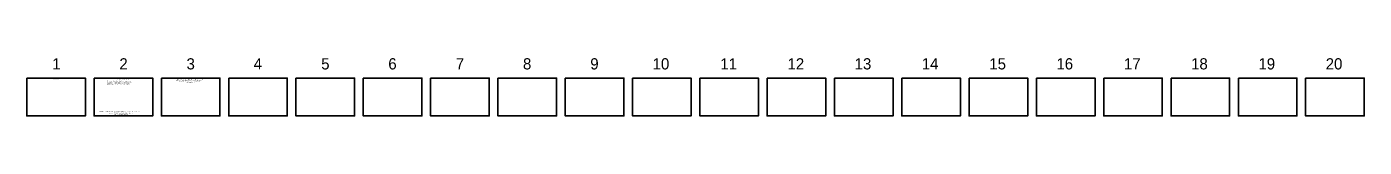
# Model space of a CAD drawing. Extents: x 10133 to 81668, y 7924 to 11018.
import ezdxf

# ---------------------------------------------------------------- set-up
doc = ezdxf.new("R2010")
doc.units = 0
for name, color, linetype in [('DisROW Survey', 7, 'Continuous'), ('Safety', 7, 'Continuous'), ('SheetBorder', 7, 'Continuous')]:
    doc.layers.add(name, color=color, linetype=linetype)

msp = doc.modelspace()

# ---------------------------------------------------------------- linework, layer by layer
at = {"layer": 'DisROW Survey'}
for points in [[(10133, 9944), (13268, 9944), (13268, 7924), (10133, 7924)], [(13733, 9944), (16868, 9944), (16868, 7924), (13733, 7924)], [(17333, 9944), (20468, 9944), (20468, 7924), (17333, 7924)], [(20933, 9944), (24068, 9944), (24068, 7924), (20933, 7924)], [(24533, 9944), (27668, 9944), (27668, 7924), (24533, 7924)], [(28133, 9944), (31268, 9944), (31268, 7924), (28133, 7924)], [(31733, 9944), (34868, 9944), (34868, 7924), (31733, 7924)], [(35333, 9944), (38468, 9944), (38468, 7924), (35333, 7924)], [(38933, 9944), (42068, 9944), (42068, 7924), (38933, 7924)], [(42533, 9944), (45668, 9944), (45668, 7924), (42533, 7924)], [(46133, 9944), (49268, 9944), (49268, 7924), (46133, 7924)], [(49733, 9944), (52868, 9944), (52868, 7924), (49733, 7924)], [(53333, 9944), (56468, 9944), (56468, 7924), (53333, 7924)], [(56933, 9944), (60068, 9944), (60068, 7924), (56933, 7924)], [(60533, 9944), (63668, 9944), (63668, 7924), (60533, 7924)], [(64133, 9944), (67268, 9944), (67268, 7924), (64133, 7924)], [(67733, 9944), (70868, 9944), (70868, 7924), (67733, 7924)], [(71333, 9944), (74468, 9944), (74468, 7924), (71333, 7924)], [(74933, 9944), (78068, 9944), (78068, 7924), (74933, 7924)], [(78533, 9944), (81668, 9944), (81668, 7924), (78533, 7924)]]:
    msp.add_lwpolyline(points, close=True, dxfattribs=at)

# ---------------------------------------------------------------- texts
at = {"layer": 'Safety'}
for s, p in [('1', (11497, 10409)), ('2', (15086, 10409)), ('3', (18678, 10409)), ('4', (22268, 10409)), ('5', (25881, 10409)), ('6', (29470, 10409)), ('7', (33080, 10409)), ('8', (36673, 10409)), ('9', (40273, 10409)), ('10', (43606, 10409)), ('11', (47230, 10409)), ('12', (50820, 10409)), ('13', (54411, 10409)), ('14', (58001, 10409)), ('15', (61614, 10409)), ('16', (65204, 10409)), ('17', (68814, 10409)), ('18', (72406, 10409)), ('19', (76007, 10409)), ('20', (79606, 10409))]:
    msp.add_text(s, height=600, dxfattribs=at).set_placement(p)
at = {"layer": 'SheetBorder'}
for s, height, p in [('Survey Information', 28, (11511, 9855)), ('This map is a guide to the vicinity of the primary project control points. ', 30, (14422, 9772)), ('control as needed for construction or other surveying applications.', 30, (14422, 9622)), ('Primary control is for use with RTK base stations and for RTN validation. ', 30, (14422, 9722)), ('Future surveys will use primary project control to establish temporary ', 30, (14422, 9672)), ('CONTROL POINT VICINITY MAP', 30, (14967, 9842)), (' HORIZ. DATUM: NAD83(2011) for EPOCH 2010.00 (IaRTN 2019 Adjustment)', 30, (18082, 9809)), ('HORIZONTAL AND VERTICAL PROJECT CONTROL COORDINATE LISTING', 30, (18110, 9865)), ('       Ia. Regional Coordinate System Zone 09 (U.S. Survey Foot)', 30, (18215, 9769)), ('VERT. DATUM: NAVD88', 30, (18651, 9717)), (' Geoid Model: 2018u3 ', 30, (18665, 9677)), (' HORIZ. DATUM: NAD83(2011) for EPOCH 2010.00 (IaRTN 2019 Adjustment) - Iowa RCS Zone 09 (U.S. Survey Foot)', 30, (13979, 8152)), ('Coordinate listing from next sheet will be used with IaRTN for monument ', 30, (14449, 8037)), ('VERT. DATUM: NAVD88 - Geoid Model: 2018u3', 30, (14762, 8094)), ('recovery. No other reference ties are given. ', 30, (14788, 7997))]:
    msp.add_text(s, height=height, dxfattribs=at).set_placement(p)

doc.saveas('drawing.dxf')
